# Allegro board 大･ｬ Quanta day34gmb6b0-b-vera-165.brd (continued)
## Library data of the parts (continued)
H19 = H-C394D354P2
H20 = H-TC177BC197D102P2
H22 = H-TC236BC102D102PT
H23 = O-Y11-1
H26 = O-Y12A-7
H27 = O-Y11A-2
H28 = O-Y12A-4
HD17 = 51625-01001-001-10P-L
J1 = SOLDERJUMPER-2
JDIM1 = DDR-DDRRK-20401-TP4B-204P-RUV
JDIM2 = DDR-DDRSK-20401-TP4B-204P-LDV
L3-L6 L8 L12 L14 L16 L36 L39-L41 L44-L46 PR14 PR19 PR68-PR70 PR80 PR97 PR119 PR161 PR165 PR168 PR175 PR176 PR178 PR180 PR186 PR208 PR219 PR220 R90 R265 R326 R328 R331 R337 R339 R341 R343 R347 R350 R355 R380 R397 R400 R409 R414 R621 R628 R7467 = RC0603
L7 L22 L27 L29 = CHOKE-WCM2012-4P
L15 = CHOKE-LQH32PN4R7NN0L
L17-L19 PR104 PR117 PR133 R342 R439 R454 = SHORT0603
L59 L60 PL1 PR7 PR11 PR61 PR237 R151 R338 R532 R598-R600 = RC0805
ODD14 = SATA-202407-2-13P-R
ODD15 = 51605-01801-001-18P-L
PC186 PC201 PC218 PC219 = ECAP5X5_8-5_9-2P
PD9 PD10 = D-DO-214AC
PJP1-PJP4 = SHORT-SOLDERJUMPER-3
PL2 = L3_2X2_5-1_55
PL3-PL7 PL15 PL17-PL19 PR114 PR125 R603 R618 = SHORT0805
PL8 PL16 PL20-PL22 = CHOKE-MPL73-1R5
PL14 = CHOKE-ETQP4L
PQ1 PQ5 PQ9 PQ34 PQ35 PQ40 PQ41 PQ44 Q10 Q13 Q15-Q25 Q29 Q31 Q37 Q39 Q40 Q7030 Q7031 = SOT23_213-3_3-2
PQ6 PQ12-PQ14 PQ18 PQ42 Q1 Q4 Q5 Q26 Q28 Q30 = UMT_213-3-1_3
PQ10 PQ31-PQ33 PQ36 PQ37 = PG-TSDSON-8-8P-R
PQ15 PQ19 PQ29 PQ30 PQ39 = SO-8FL-5P
PQ16 PQ17 Q3 Q12 Q14 Q27 Q34 Q38 Q41 Q820 Q821 = SC70-2_1-65-6P
PQ20 = TO252_134-9_9-4_57-SMT
PQ38 = SOT363-2_1-65-6P
PQ43 PU4 = TSOP6-2_8-95
PR109 PR123 PR127 PR136 PR138 PR158 PR159 PR167 PR170 PR187-PR189 PR221 PR222 = SHORT0201
PR137 PR211 = F3_2X1_65-2_8
PU1 = PVQFN20-3_5X3_5-5-25P
PU3 = QFN28-4X4-4-29P-NCP81101MNTWG
PU5 PU8 = SON14-3X2-4-15P
PU7 = WQFN20-3X3-4-21P
PU10 = QFN23-4X4-5
PU11 PU12 = QFN10-3X3-45
RP1 = 4P2R-0404
RP2-RP6 = 10P8R
TP3-TP6 TP12 TP13 TP21 TP22 TP26 TP27 TP32-TP34 TP36 = TP2650
TP7-TP9 TP23 TP24 TP28-TP30 TP35 = TP2675
TP10 TP11 TP20 TP25 TP31 = TP2050
TP51 = TP1250-P14_4
U2 U17 U22 U26 = SOT23-5
U6 U7 = TRF-9_6-1_27-16P
U8 = QFN32-4X4-4-33P-0_9H
U9 = TQFN16-2X3-4-17P
U10 = QFN16-3X3-5-17P-WM9001
U11 = LQFP128-16X16-4
U12 = VQFN14-3_5X3_5-5-15P
U13 = LGA16-3X3-5-HP3DC2TR
U14 = TSSOP28-6_4-65-29P-1_2H
U15 U8021 = TQFN24-4X4-5-34P
U16 U27 = MSOP8-4_9-65
U18 = TSSOP28-6_4-65
U19 = QFN32-4X4-5-33P-RTS5227-GRT
U20 = QFN48-7X7-5-49P-1H
U21 U28 = PWQFN20-4X4-5-30P
U23 = 91960-0084L-8P-SOCKET
U24 = SOIC8-8-1_27
U25 = BGA1168-INTEL-HASWELL
Y1 = XTL-3_2X2_5-2_2X1_7-0_8H
Y2 Y3 = XTL-3_2X2_5-2_2X1_7
Y4 = XTL-3_2X1_5-2_5-0_8H

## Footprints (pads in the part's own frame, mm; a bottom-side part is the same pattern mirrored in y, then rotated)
4P2R-0404
  rect 0.33x0.762 smd: 1(-0.325,-0.5) 2(-0.325,0.5) 3(0.325,-0.5) 4(0.325,0.5)
10P8R
  rect 0.305x1.092 smd: 1(-1.27,-0.85) 2(-0.635,-0.85) 3(0,-0.85) 4(0.635,-0.85) 5(1.27,-0.85) 6(1.27,0.85) 7(0.635,0.85) 8(0,0.85) 9(-0.635,0.85) 10(-1.27,0.85)
50273-0040L-001-4P-L
  rect 0.787x1.6 smd: 1(-1.875,2.9) 2(-0.625,2.9) 3(0.625,2.9) 4(1.875,2.9)
  rect 2.108x2.997 smd: 5(-4.425,0) 6(4.425,0)
50281-00401-001-4P-L
  rect 0.787x2.007 smd: 1(-1.875,4.05) 2(-0.625,4.05) 3(0.625,4.05) 4(1.875,4.05)
  rect 2.007x2.489 smd: 5(-4.075,0) 6(4.075,0)
50501-03001-001-30P-L
  rect 0.305x1.295 smd: 1(-7.25,2.8) 2(-6.75,2.8) 3(-6.25,2.8) 4(-5.75,2.8) 5(-5.25,2.8) 6(-4.75,2.8) 7(-4.25,2.8) 8(-3.75,2.8) 9(-3.25,2.8) 10(-2.75,2.8) 11(-2.25,2.8) 12(-1.75,2.8) 13(-1.25,2.8) 14(-0.75,2.8) 15(-0.25,2.8) 16(0.25,2.8) 17(0.75,2.8) 18(1.25,2.8) 19(1.75,2.8) 20(2.25,2.8) 21(2.75,2.8) 22(3.25,2.8) 23(3.75,2.8) 24(4.25,2.8) 25(4.75,2.8) 26(5.25,2.8) 27(5.75,2.8) 28(6.25,2.8) 29(6.75,2.8) 30(7.25,2.8)
  rect 1.803x1.397 smd: 31(-8.9,0) 32(8.9,0)
50505-0040N-V01-4P-L
  rect 0.61x1.295 smd: 1(-1.5,3.25) 2(-0.5,3.25) 3(0.5,3.25) 4(1.5,3.25)
  rect 0.991x2.007 smd: 5(-4.1,0) 6(4.1,0)
50519-00801-V01-8P-L
  rect 0.508x1.295 smd: 1(-2.8,3.05) 2(-2,3.05) 3(-1.2,3.05) 4(-0.4,3.05) 5(0.4,3.05) 6(1.2,3.05) 7(2,3.05) 8(2.8,3.05)
  rect 1.803x1.905 smd: 9(-5.1,0) 10(5.1,0)
51540-0404T-001-40P-L
  rect 0.305x0.838 smd: 1(-9.75,3.175) 2(-9.25,3.175) 3(-8.75,3.175) 4(-8.25,3.175) 5(-7.75,3.175) 6(-7.25,3.175) 7(-6.75,3.175) 8(-6.25,3.175) 9(-5.75,3.175) 10(-5.25,3.175) 11(-4.75,3.175) 12(-4.25,3.175) 13(-3.75,3.175) 14(-3.25,3.175) 15(-2.75,3.175) 16(-2.25,3.175) 17(-1.75,3.175) 18(-1.25,3.175) 19(-0.75,3.175) 20(-0.25,3.175) 21(0.25,3.175) 22(0.75,3.175) 23(1.25,3.175) 24(1.75,3.175) 25(2.25,3.175) 26(2.75,3.175) 27(3.25,3.175) 28(3.75,3.175) 29(4.25,3.175) 30(4.75,3.175) 31(5.25,3.175) 32(5.75,3.175) 33(6.25,3.175) 34(6.75,3.175) 35(7.25,3.175) 36(7.75,3.175) 37(8.25,3.175) 38(8.75,3.175) 39(9.25,3.175) 40(9.75,3.175)
  rect 0.787x2.007 smd: 41(-11.45,0) 42(11.45,0)
51586-03241-001-32P-L
  rect 0.406x0.838 smd: 1(-15.5,3.175) 2(-14.5,3.175) 3(-13.5,3.175) 4(-12.5,3.175) 5(-11.5,3.175) 6(-10.5,3.175) 7(-9.5,3.175) 8(-8.5,3.175) 9(-7.5,3.175) 10(-6.5,3.175) 11(-5.5,3.175) 12(-4.5,3.175) 13(-3.5,3.175) 14(-2.5,3.175) 15(-1.5,3.175) 16(-0.5,3.175) 17(0.5,3.175) 18(1.5,3.175) 19(2.5,3.175) 20(3.5,3.175) 21(4.5,3.175) 22(5.5,3.175) 23(6.5,3.175) 24(7.5,3.175) 25(8.5,3.175) 26(9.5,3.175) 27(10.5,3.175) 28(11.5,3.175) 29(12.5,3.175) 30(13.5,3.175) 31(14.5,3.175) 32(15.5,3.175)
  rect 0.787x2.007 smd: 33(-17.7,0) 34(17.7,0)
51605-01801-001-18P-L
  rect 0.305x0.838 smd: 1(-4.25,3.175) 2(-3.75,3.175) 3(-3.25,3.175) 4(-2.75,3.175) 5(-2.25,3.175) 6(-1.75,3.175) 7(-1.25,3.175) 8(-0.75,3.175) 9(-0.25,3.175) 10(0.25,3.175) 11(0.75,3.175) 12(1.25,3.175) 13(1.75,3.175) 14(2.25,3.175) 15(2.75,3.175) 16(3.25,3.175) 17(3.75,3.175) 18(4.25,3.175)
  rect 0.787x2.007 smd: 19(-5.95,0) 20(5.95,0)
51625-01001-001-10P-L
  rect 0.305x0.838 smd: 1(-2.25,3.175) 2(-1.75,3.175) 3(-1.25,3.175) 4(-0.75,3.175) 5(-0.25,3.175) 6(0.25,3.175) 7(0.75,3.175) 8(1.25,3.175) 9(1.75,3.175) 10(2.25,3.175)
  rect 0.787x2.007 smd: 11(-3.95,0) 12(3.95,0)
59012-0080N-003-8P-LDV-SMT
  round 1.27 hole 0.991: 1(-3,-1) 2(-3,1) 3(-1,-1) 4(-1,1) 5(1,-1) 6(1,1) 7(3,-1) 8(3,1)
88266-020L-2P-L-SMT
  rect 0.787x2.007 smd: 1(-0.625,4.05) 2(0.625,4.05)
  rect 1.346x1.6 smd: 3(-2.5,-0.45) 4(2.5,-0.45)
88266-0400-4P-L
  rect 0.787x2.007 smd: 1(-1.875,4.05) 2(-0.625,4.05) 3(0.625,4.05) 4(1.875,4.05)
  rect 2.007x2.489 smd: 5(-4.075,0) 6(4.075,0)
88511-180N-18P-L
  rect 0.305x1.295 smd: 1(-4.25,2.8) 2(-3.75,2.8) 3(-3.25,2.8) 4(-2.75,2.8) 5(-2.25,2.8) 6(-1.75,2.8) 7(-1.25,2.8) 8(-0.75,2.8) 9(-0.25,2.8) 10(0.25,2.8) 11(0.75,2.8) 12(1.25,2.8) 13(1.75,2.8) 14(2.25,2.8) 15(2.75,2.8) 16(3.25,2.8) 17(3.75,2.8) 18(4.25,2.8)
  rect 1.803x1.397 smd: 19(-5.9,0) 20(5.9,0)
88513-0601-6P-L-SMT
  rect 0.508x1.6 smd: 1(-2.5,2.95) 2(-1.5,2.95) 3(-0.5,2.95) 4(0.5,2.95) 5(1.5,2.95) 6(2.5,2.95)
  rect 1.803x1.397 smd: 7(-4.65,0) 8(4.65,0)
88513-2001-20P-L
  rect 0.508x1.295 smd: 1(-9.5,0) 2(-8.5,0) 3(-7.5,0) 4(-6.5,0) 5(-5.5,0) 6(-4.5,0) 7(-3.5,0) 8(-2.5,0) 9(-1.5,0) 10(-0.5,0) 11(0.5,0) 12(1.5,0) 13(2.5,0) 14(3.5,0) 15(4.5,0) 16(5.5,0) 17(6.5,0) 18(7.5,0) 19(8.5,0) 20(9.5,0)
  rect 1.803x1.397 smd: 21(-11.65,-2.8) 22(11.65,-2.8)
91960-0084L-8P-SOCKET
  rect 0.889x1.346 smd: 1(1.905,3.675) 2(0.635,3.675) 3(-0.635,3.675) 4(-1.905,3.675) 5(-1.905,-3.675) 6(-0.635,-3.675) 7(0.635,-3.675) 8(1.905,-3.675)
BAT-23_2-4_2
  round 0.787 hole 0.787 unplated: (0,-8)
  round 1.194 hole 1.194 unplated: (0,8)
  rect 2.007x3.988 smd: 1(14.5,0) 2(-15.8,0)
BAT-PMPCRT-08MLBK2ZZ4H0-8P-L
  round 1.6 hole 0.991: 1(-7,0) 2(-5,0) 3(-3,0) 4(-1,0) 5(1,0) 6(3,0) 7(5,0) 8(7,0)
  oval 2.007x3.607 hole 0.787x2.692: 9(-9.625,1.2) 10(9.625,0)
  round 4.216 hole 3.2: 11(14.75,-6.8)
BAT-PMPCRT-08MLBK2ZZ4H1-8P-L
  round 1.6 hole 0.991: 1(-7,0) 2(-5,0) 3(-3,0) 4(-1,0) 5(1,0) 6(3,0) 7(5,0) 8(7,0)
  oval 2.007x3.607 hole 0.787x2.692: 9(-9.625,1.2) 10(9.625,0)
  round 4.216 hole 3.2: 11(19,0.7)
BGA1168-INTEL-HASWELL
  round 0.508 smd: A3(18.177,-11.314) A62(-18.722,-11.314) AW1(19.314,10.727) AW63(-19.314,10.743) AY2(18.771,11.314) AY62(-18.748,11.314) B2(18.806,-10.806) B63(-19.314,-10.722) C1(19.314,-10.177)
  round 0.381 smd: A4(17.421,-11.314) A5(16.76,-11.314) A6(15.564,-11.314) A59(-16.586,-11.314) A60(-17.412,-11.314) A61(-18.072,-11.314) AA9(14.282,0.262) AA21(7.627,0.175) AA23(6.199,0.175) AA58(-16.063,0.015) AB10(13.838,0.738) AB20(8.135,0.582) AB21(7.627,0.988) AB22(6.707,0.582) AB23(6.199,0.988) AB57(-15.743,0.666) AC9(14.282,1.215) AC20(8.135,1.394) AC22(6.707,1.394) AC58(-16.063,1.316) AD10(13.838,1.691) AD21(7.627,1.801) AD23(6.199,1.801) AD57(-15.743,1.966) AE9(14.282,2.167) AE10(13.838,2.643) AE20(8.135,2.207) AE21(7.627,2.614) AE22(6.707,2.207) AE23(6.199,2.614) AE58(-16.063,2.616) AF9(14.282,3.12) AF11(13.255,2.968) AF12(12.442,2.968) AF14(11.63,2.968) AF15(10.817,2.968) AF17(10.004,2.968) AF18(9.191,2.968) AF20(8.378,2.968) AF22(6.707,3.02) AG10(13.662,3.476) AG11(12.849,3.476) AG13(12.036,3.476) AG14(11.223,3.476) AG16(10.41,3.476) AG17(9.598,3.476) AG19(8.785,3.476) AG20(7.972,3.476) AG23(6.199,3.426) AG57(-15.743,3.267) AG58(-16.377,3.695) AH22(6.707,3.833) AH24(5.394,3.975) AH26(4.094,3.975) AH28(2.793,3.975) AH30(1.493,3.975) AH32(0.192,3.975) AH34(-1.108,3.975) AH36(-2.409,3.975) AH38(-3.709,3.975) AH40(-5.01,3.975) AH42(-6.31,3.975) AH44(-7.611,3.975) AH46(-8.911,3.975) AH49(-10.212,3.975) AH51(-11.512,3.975) AH53(-12.813,3.975) AH55(-14.113,3.975) AH57(-15.413,3.975) AJ23(6.199,4.239) AJ25(4.744,4.3) AJ27(3.443,4.3) AJ29(2.143,4.3) AJ31(0.843,4.3) AJ33(-0.458,4.3) AJ35(-1.758,4.3) AJ37(-3.059,4.3) AJ39(-4.359,4.3) AJ41(-5.66,4.3) AJ43(-6.96,4.3) AJ45(-8.261,4.3) AJ47(-9.561,4.3) AJ50(-10.862,4.3) AJ52(-12.162,4.3) AJ54(-13.463,4.3) AJ56(-14.763,4.3) AJ58(-16.064,4.3) AT1(19.314,8.683) AT63(-19.314,8.533) AU1(19.314,9.343) AU63(-19.314,9.359) AV1(19.314,10.004) AV2(18.654,9.993) AV62(-18.664,10.004) AV63(-19.314,10.019) AW2(18.654,10.654) AW3(17.993,10.654) AW61(-18.014,10.664) AW62(-18.664,10.664) AY3(18.047,11.314) AY4(17.387,11.314) AY5(16.726,11.314) AY59(-16.774,11.314) AY60(-17.434,11.314) AY61(-18.095,11.314) B3(18.056,-10.664) B61(-18.001,-10.654) B62(-18.664,-10.59) C2(18.664,-10.056) C62(-18.664,-9.93) C63(-19.314,-9.998) D1(19.314,-9.453) D63(-19.314,-9.338) E1(19.314,-8.792) E23(5.981,-8.713) E25(4.6,-8.713) E27(3.474,-8.713) E29(2.093,-8.713) E31(0.966,-8.713) E33(-0.415,-8.713) E35(-1.541,-8.713) E37(-2.922,-8.713) E39(-4.049,-8.713) E41(-5.43,-8.713) E43(-6.556,-8.713) E45(-7.937,-8.713) E47(-9.064,-8.713) E49(-10.444,-8.713) E51(-11.571,-8.713) E53(-12.952,-8.713) E55(-14.079,-8.713) E57(-15.459,-8.713) E63(-19.314,-8.667) F1(19.314,-7.878) F22(6.597,-8.256) F24(5.291,-8.188) F26(4.037,-8.188) F28(2.783,-8.188) F30(1.53,-8.188) F32(0.276,-8.188) F34(-0.978,-8.188) F36(-2.232,-8.188) F38(-3.485,-8.188) F40(-4.739,-8.188) F42(-5.993,-8.188) F44(-7.247,-8.188) F46(-8.5,-8.188) F48(-9.754,-8.188) F50(-11.008,-8.188) F52(-12.262,-8.188) F54(-13.515,-8.188) F56(-14.769,-8.188) F58(-16.063,-8.188) G22(6.707,-7.546) G23(5.981,-7.863) G25(4.6,-7.863) G27(3.474,-7.863) G29(2.093,-7.863) G31(0.966,-7.863) G33(-0.415,-7.863) G35(-1.541,-7.863) G37(-2.922,-7.863) G39(-4.049,-7.863) G41(-5.43,-7.863) G43(-6.556,-7.863) G45(-7.937,-7.863) G47(-9.064,-7.863) G49(-10.444,-7.863) G51(-11.571,-7.863) G53(-12.952,-7.863) G55(-14.079,-7.863) G57(-15.459,-7.863) H22(6.707,-6.734) H23(6.199,-7.14) H57(-15.743,-7.213) J22(6.707,-5.921) J23(6.199,-6.327) J58(-16.063,-6.487) K9(14.282,-5.453) K10(13.379,-5.614) K12(12.426,-5.614) K14(11.474,-5.614) K16(10.521,-5.614) K18(9.569,-5.614) K19(8.616,-5.614) K21(7.664,-5.614) K23(6.199,-5.514) K57(-15.743,-5.837) L10(13.838,-4.977) L11(12.902,-5.17) L13(11.95,-5.17) L15(10.997,-5.17) L17(10.045,-5.17) L18(9.092,-5.17) L20(8.135,-5.108) L22(6.707,-5.108) L58(-16.063,-5.186) M9(14.282,-4.5) M20(8.135,-4.295) M21(7.627,-4.702) M22(6.707,-4.295) M23(6.199,-4.702) M57(-15.743,-4.536) N10(13.838,-4.024) N21(7.627,-3.889) N23(6.199,-3.889) N58(-16.063,-3.886) P9(14.282,-3.548) P20(8.135,-3.482) P22(6.707,-3.482) P57(-15.743,-3.236) R10(13.838,-3.072) R20(8.135,-2.67) R21(7.627,-3.076) R22(6.707,-2.67) R23(6.199,-3.076) T9(14.282,-2.595) T21(7.627,-2.263) T23(6.199,-2.263) T58(-16.063,-2.585) U9(14.282,-1.643) U10(13.838,-2.119) U20(8.135,-1.857) U22(6.707,-1.857) U57(-15.743,-1.935) V10(13.838,-1.167) V21(7.627,-1.45) V23(6.199,-1.45) V58(-16.063,-1.285) W9(14.282,-0.69) W20(8.135,-1.044) W21(7.627,-0.638) W22(6.707,-1.044) W23(6.199,-0.638) W57(-15.743,-0.635) Y10(13.838,-0.214) Y20(8.135,-0.231) Y22(6.707,-0.231)
  round 0.305 smd: A8(14.776,-11.314) A9(13.862,-11.314) A11(12.948,-11.314) A12(12.198,-11.314) A14(11.284,-11.314) A15(10.37,-11.314) A17(9.62,-11.314) A18(8.706,-11.314) A20(7.791,-11.314) A21(7.042,-11.314) A23(6.128,-11.314) A24(5.291,-10.989) A25(4.6,-11.314) A27(3.474,-11.314) A28(2.783,-10.989) A29(2.093,-11.314) A31(0.966,-11.314) A32(0.276,-10.989) A33(-0.415,-11.314) A35(-1.541,-11.314) A36(-2.232,-10.989) A37(-2.922,-11.314) A39(-4.049,-11.314) A40(-4.739,-10.989) A41(-5.43,-11.314) A43(-6.556,-11.314) A44(-7.247,-10.989) A45(-7.937,-11.314) A47(-9.064,-11.314) A48(-9.754,-10.989) A49(-10.444,-11.314) A51(-11.571,-11.314) A52(-12.262,-10.989) A53(-12.952,-11.314) A55(-14.079,-11.314) A56(-14.769,-10.989) A57(-15.459,-11.314) AA1(19.314,0.402) AA2(18.664,0.402) AA3(18.014,0.364) AA4(17.363,0.364) AA59(-16.713,0.324) AA60(-17.363,0.324) AA61(-18.014,0.324) AA62(-18.664,0.362) AA63(-19.314,0.362) AB5(16.678,0.738) AB6(16.027,0.738) AB7(15.377,0.738) AB8(14.727,0.738) AC1(19.314,1.152) AC2(18.664,1.152) AC3(18.014,1.19) AC4(17.363,1.19) AC59(-16.713,1.15) AC60(-17.363,1.15) AC61(-18.014,1.15) AC62(-18.664,1.112) AC63(-19.314,1.112) AD1(19.314,1.901) AD2(18.664,1.901) AD3(18.014,1.863) AD4(17.363,1.863) AD5(16.678,1.691) AD6(16.027,1.691) AD7(15.377,1.691) AD8(14.727,1.691) AD59(-16.713,1.823) AD60(-17.363,1.823) AD61(-18.014,1.823) AD62(-18.664,1.861) AD63(-19.314,1.861) AE5(16.678,2.643) AE6(16.027,2.643) AE7(15.377,2.643) AE8(14.727,2.643) AE59(-16.713,2.648) AE60(-17.363,2.648) AE61(-18.014,2.648) AE62(-18.664,2.61) AE63(-19.314,2.61) AF1(19.314,2.65) AF2(18.664,2.65) AF3(18.014,2.688) AF4(17.363,2.688) AG1(19.314,3.4) AG2(18.664,3.4) AG3(18.014,3.361) AG4(17.363,3.361) AG5(16.678,3.596) AG6(16.027,3.596) AG7(15.377,3.596) AG8(14.727,3.596) AG21(7.359,3.807) AG60(-17.038,3.288) AG61(-17.689,3.288) AG62(-18.339,3.288) AG63(-18.989,3.288) AH1(19.314,4.149) AH2(18.664,4.149) AH3(18.014,4.187) AH4(17.363,4.187) AH10(13.662,4.162) AH11(12.849,4.162) AH13(12.036,4.162) AH14(11.223,4.162) AH16(10.41,4.162) AH17(9.598,4.162) AH19(8.785,4.162) AH20(7.972,4.162) AH60(-17.363,3.964) AH61(-18.014,3.964) AH62(-18.664,3.964) AH63(-19.314,3.964) AJ5(16.678,4.548) AJ6(16.027,4.548) AJ7(15.377,4.548) AJ8(14.727,4.548) AJ10(13.662,4.812) AJ11(12.849,4.812) AJ13(12.036,4.812) AJ14(11.223,4.812) AJ60(-17.038,4.64) AJ61(-17.689,4.64) AJ62(-18.339,4.64) AJ63(-18.989,4.64) AK1(19.314,4.898) AK2(18.664,4.898) AK3(18.014,4.86) AK4(17.363,4.86) AK8(15.011,5.137) AK18(9.466,4.952) AK20(8.513,4.952) AK21(7.561,4.952) AK60(-17.363,5.209) AK61(-18.014,5.209) AK62(-18.664,5.315) AK63(-19.314,5.315) AL1(19.314,5.647) AL2(18.664,5.647) AL3(18.014,5.686) AL4(17.363,5.686) AL5(16.413,5.462) AL7(15.575,5.462) AL8(15.011,5.787) AL10(13.657,5.462) AL11(13.093,5.787) AL13(11.738,5.462) AL15(11.174,5.787) AL17(10.092,5.268) AL18(9.466,5.602) AL20(8.513,5.602) AL21(7.561,5.602) AL22(6.608,5.602) AL23(5.786,5.602) AL25(4.81,5.602) AL26(3.858,5.602) AL28(2.905,5.602) AL29(1.953,5.602) AL31(1.054,5.277) AL32(0.49,5.602) AL33(-0.412,5.602) AL35(-1.415,5.602) AL36(-2.266,5.602) AL38(-3.32,5.602) AL39(-4.228,5.277) AL40(-4.817,5.602) AL42(-5.63,5.602) AL43(-6.582,5.602) AL45(-7.56,5.602) AL46(-8.487,5.602) AL48(-9.542,5.602) AL49(-10.443,5.602) AL51(-11.447,5.602) AL52(-12.269,5.602) AL54(-13.295,5.602) AL55(-14.248,5.602) AL57(-15.195,5.602) AL58(-16.094,5.602) AL60(-17.038,5.855) AL61(-17.689,5.855) AM1(19.314,6.397) AM2(18.664,6.397) AM3(18.014,6.359) AM4(17.363,6.359) AM5(16.413,6.112) AM7(15.575,6.112) AM8(15.011,6.437) AM10(13.657,6.112) AM11(13.093,6.437) AM13(11.738,6.112) AM15(11.174,6.437) AM17(10.092,5.919) AM18(9.466,6.252) AM20(8.513,6.252) AM21(7.561,6.252) AM22(6.608,6.252) AM23(5.786,6.252) AM25(4.81,6.252) AM26(3.858,6.252) AM28(2.905,6.252) AM29(1.953,6.252) AM31(1.054,5.927) AM32(0.49,6.252) AM33(-0.412,6.252) AM35(-1.415,6.252) AM36(-2.266,6.252) AM38(-3.32,6.252) AM40(-4.817,6.252) AM42(-5.63,6.252) AM43(-6.582,6.252) AM45(-7.56,6.252) AM46(-8.487,6.252) AM48(-9.542,6.252) AM49(-10.443,6.252) AM51(-11.447,6.252) AM52(-12.269,6.252) AM54(-13.295,6.252) AM55(-14.248,6.252) AM57(-15.195,6.252) AM58(-16.094,6.252) AM60(-17.363,6.501) AM61(-18.014,6.501) AM62(-18.664,6.395) AM63(-19.314,6.395) AN1(19.314,7.146) AN2(18.664,7.146) AN3(18.014,7.184) AN4(17.363,7.184) AN5(16.413,6.762) AN7(15.575,6.762) AN8(15.011,7.088) AN10(13.657,6.762) AN11(13.093,7.088) AN13(11.738,6.762) AN15(11.174,7.088) AN17(10.092,6.569) AN18(9.466,6.903) AN20(8.513,6.903) AN21(7.561,6.903) AN22(6.608,6.903) AN23(5.786,6.903) AN25(4.81,6.903) AN26(3.858,6.903) AN28(2.905,6.903) AN29(1.953,6.903) AN31(1.054,6.578) AN32(0.49,6.903) AN33(-0.412,6.903) AN35(-1.415,6.903) AN36(-2.266,6.903) AN38(-3.32,6.903) AN39(-4.228,6.578) AN40(-4.817,6.903) AN42(-5.63,6.903) AN43(-6.582,6.903) AN45(-7.56,6.903) AN46(-8.487,6.903) AN48(-9.542,6.903) AN49(-10.443,6.903) AN51(-11.447,6.903) AN52(-12.269,6.903) AN54(-13.295,6.903) AN55(-14.248,6.903) AN57(-15.195,6.903) AN58(-16.094,6.903) AN60(-17.038,7.07) AN61(-17.689,7.07) AN62(-18.339,7.07) AN63(-18.989,7.07) AP1(19.314,7.895) AP2(18.664,7.895) AP3(18.014,7.857) AP4(17.363,7.857) AP5(16.413,7.413) AP7(15.575,7.413) AP8(15.011,7.738) AP10(13.657,7.413) AP11(13.093,7.738) AP13(11.738,7.413) AP15(11.174,7.738) AP17(10.092,7.219) AP18(9.466,7.553) AP20(8.513,7.553) AP21(7.561,7.553) AP22(6.608,7.553) AP23(5.786,7.553) AP25(4.81,7.553) AP26(3.858,7.553) AP28(2.905,7.553) AP29(1.953,7.553) AP31(1.054,7.228) AP32(0.49,7.553) AP33(-0.412,7.553) AP35(-1.415,7.553) AP36(-2.266,7.553) AP38(-3.32,7.553) AP39(-4.228,7.228) AP40(-4.817,7.553) AP42(-5.63,7.553) AP43(-6.582,7.553) AP45(-7.56,7.553) AP46(-8.487,7.553) AP48(-9.542,7.553) AP49(-10.443,7.553) AP51(-11.447,7.553) AP52(-12.269,7.553) AP54(-13.295,7.553) AP55(-14.248,7.553) AP57(-15.195,7.553) AP58(-16.094,7.553) AP60(-17.363,7.746) AP61(-18.014,7.746) AP62(-18.664,7.746) AP63(-19.314,7.746) AR5(16.413,8.063) AR7(15.575,8.063) AR8(15.011,8.388) AR10(13.657,8.063) AR11(13.093,8.388) AR13(11.738,8.063) AR15(11.174,8.388) AR17(10.092,7.869) AR18(9.466,8.203) AR20(8.513,8.203) AR21(7.561,8.203) AR22(6.608,8.203) AR23(5.786,8.203) AR25(4.81,8.203) AR26(3.858,8.203) AR28(2.905,8.203) AR29(1.953,8.203) AR31(1.054,7.878) AR32(0.49,8.203) AR33(-0.412,8.203) AR35(-1.415,8.203) AR36(-2.266,8.203) AR38(-3.32,8.203) AR39(-4.228,7.878) AR40(-4.817,8.203) AR42(-5.63,8.203) AR43(-6.582,8.203) AR45(-7.56,8.203) AR46(-8.487,8.203) AR48(-9.542,8.203) AR49(-10.443,8.203) AR51(-11.447,8.203) AR52(-12.269,8.203) AR54(-13.295,8.203) AR55(-14.248,8.203) AR57(-15.195,8.203) AR58(-16.094,8.203) AT2(18.664,8.645) AT3(18.014,8.683) AT4(17.363,8.683) AT5(16.413,8.713) AT7(15.575,8.713) AT10(13.657,8.713) AT13(11.738,8.713) AT35(-1.122,8.905) AT37(-2.697,8.905) AT40(-4.272,8.905) AT42(-5.847,8.905) AT43(-7.422,8.905) AT46(-8.996,8.905) AT49(-10.597,8.933) AT61(-17.689,8.32) AT62(-18.498,8.376) AU2(18.659,9.333) AU3(17.999,9.333) AU4(17.338,9.333) AU6(15.977,9.363) AU7(15.151,9.363) AU8(14.478,9.363) AU10(13.653,9.363) AU11(12.98,9.363) AU12(12.154,9.363) AU14(11.481,9.363) AU15(10.656,9.363) AU16(10.092,9.038) AU17(9.454,9.363) AU18(8.778,9.038) AU19(8.21,9.363) AU20(7.563,9.038) AU21(6.917,9.363) AU22(6.348,9.038) AU23(5.672,9.363) AU24(4.996,9.038) AU25(4.321,9.363) AU26(3.645,9.038) AU27(3.076,9.363) AU28(2.43,9.038) AU29(1.783,9.363) AU30(1.214,9.038) AU31(0.539,9.363) AU33(-0.058,9.016) AU34(-0.66,9.363) AU35(-1.585,9.363) AU36(-2.235,9.363) AU37(-3.16,9.363) AU39(-3.81,9.363) AU40(-4.734,9.363) AU41(-5.385,9.363) AU42(-6.309,9.363) AU43(-6.959,9.363) AU44(-7.884,9.363) AU46(-8.534,9.363) AU47(-9.459,9.363) AU49(-10.109,9.363) AU50(-11.086,9.363) AU51(-11.666,9.038) AU52(-12.342,9.363) AU53(-13.017,9.038) AU54(-13.586,9.363) AU55(-14.233,9.038) AU56(-14.879,9.363) AU57(-15.448,9.038) AU58(-16.124,9.363) AU59(-16.688,9.038) AU60(-17.251,9.363) AU61(-17.963,9.087) AU62(-18.664,9.349) AV3(17.993,9.993) AV4(17.338,9.993) AV5(16.65,10.014) AV6(15.977,10.014) AV7(15.151,10.014) AV8(14.478,10.014) AV10(13.653,10.014) AV11(12.98,10.014) AV12(12.154,10.014) AV14(11.481,10.014) AV15(10.656,10.014) AV16(10.092,9.689) AV17(9.454,10.014) AV18(8.778,9.689) AV19(8.21,10.014) AV20(7.563,9.689) AV21(6.917,10.014) AV22(6.348,9.689) AV23(5.672,10.014) AV24(4.996,9.689) AV25(4.321,10.014) AV26(3.645,9.689) AV27(3.076,10.014) AV28(2.43,9.689) AV29(1.783,10.014) AV30(1.214,9.689) AV31(0.539,10.014) AV33(-0.086,9.689) AV34(-0.71,10.014) AV35(-1.535,10.014) AV36(-2.284,10.014) AV37(-3.11,10.014) AV39(-3.859,10.014) AV40(-4.685,10.014) AV41(-5.434,10.014) AV42(-6.26,10.014) AV43(-7.009,10.014) AV44(-7.834,10.014) AV46(-8.584,10.014) AV47(-9.409,10.014) AV49(-10.158,10.014) AV50(-10.984,10.014) AV51(-11.666,9.689) AV52(-12.342,10.014) AV53(-13.017,9.689) AV54(-13.586,10.014) AV55(-14.233,9.689) AV56(-14.879,10.014) AV57(-15.448,9.689) AV58(-16.124,10.014) AV59(-16.688,9.689) AV60(-17.251,10.014) AV61(-17.988,9.737) AW4(17.338,10.654) AW5(16.688,10.664) AW6(15.939,10.664) AW7(15.189,10.664) AW8(14.44,10.664) AW10(13.691,10.664) AW11(12.942,10.664) AW12(12.192,10.664) AW14(11.443,10.664) AW15(10.694,10.664) AW16(10.092,10.339) AW17(9.454,10.664) AW18(8.778,10.339) AW19(8.103,10.664) AW21(7.023,10.664) AW22(6.348,10.339) AW23(5.672,10.664) AW24(4.996,10.339) AW25(4.321,10.664) AW26(3.645,10.339) AW27(2.97,10.664) AW29(1.89,10.664) AW30(1.214,10.339) AW31(0.539,10.664) AW33(-0.137,10.339) AW34(-0.71,10.664) AW35(-1.535,10.664) AW36(-2.284,10.664) AW37(-3.11,10.664) AW39(-3.859,10.664) AW40(-4.685,10.664) AW41(-5.434,10.664) AW42(-6.26,10.664) AW43(-7.009,10.664) AW44(-7.834,10.664) AW46(-8.584,10.664) AW47(-9.409,10.664) AW49(-10.158,10.664) AW50(-10.984,10.664) AW51(-11.666,10.339) AW52(-12.342,10.664) AW53(-13.017,10.339) AW54(-13.693,10.664) AW56(-14.772,10.664) AW57(-15.448,10.339) AW58(-16.124,10.664) AW59(-16.688,10.339) AW60(-17.251,10.664) AY6(15.939,11.314) AY7(15.189,11.314) AY8(14.44,11.314) AY10(13.691,11.314) AY11(12.942,11.314) AY12(12.192,11.314) AY14(11.443,11.314) AY15(10.694,11.314) AY16(10.13,10.989) AY17(9.454,11.314) AY18(8.778,10.989) AY19(8.103,11.314) AY21(7.023,11.314) AY22(6.348,10.989) AY23(5.672,11.314) AY24(4.996,10.989) AY25(4.321,11.314) AY26(3.645,10.989) AY27(2.97,11.314) AY29(1.89,11.314) AY30(1.214,10.989) AY31(0.539,11.314) AY33(-0.137,10.989) AY34(-0.71,11.314) AY35(-1.535,11.314) AY36(-2.284,11.314) AY37(-3.11,11.314) AY39(-3.859,11.314) AY40(-4.685,11.314) AY41(-5.434,11.314) AY42(-6.26,11.314) AY43(-7.009,11.314) AY44(-7.834,11.314) AY46(-8.584,11.314) AY47(-9.409,11.314) AY49(-10.158,11.314) AY50(-10.984,11.314) AY51(-11.666,10.989) AY52(-12.342,11.314) AY53(-13.017,10.989) AY54(-13.693,11.314) AY56(-14.772,11.314) AY57(-15.448,10.989) AY58(-16.124,11.314) B4(17.393,-10.664) B5(16.176,-10.672) B6(15.196,-10.672) B8(14.423,-10.672) B9(13.598,-10.672) B11(12.617,-10.672) B12(11.845,-10.672) B14(11.02,-10.672) B15(10.039,-10.672) B17(9.267,-10.672) B18(8.442,-10.672) B20(7.461,-10.672) B21(7.042,-10.118) B22(6.689,-10.672) B23(5.864,-10.672) B24(5.291,-10.339) B25(4.6,-10.664) B26(4.037,-10.339) B27(3.474,-10.664) B28(2.783,-10.339) B29(2.093,-10.664) B30(1.53,-10.339) B31(0.966,-10.664) B32(0.276,-10.339) B33(-0.415,-10.664) B34(-0.978,-10.339) B35(-1.541,-10.664) B36(-2.232,-10.339) B37(-2.922,-10.664) B38(-3.485,-10.339) B39(-4.049,-10.664) B40(-4.739,-10.339) B41(-5.43,-10.664) B42(-5.993,-10.339) B43(-6.556,-10.664) B44(-7.247,-10.339) B45(-7.937,-10.664) B46(-8.5,-10.339) B47(-9.064,-10.664) B48(-9.754,-10.339) B49(-10.444,-10.664) B50(-11.008,-10.339) B51(-11.571,-10.664) B52(-12.262,-10.339) B53(-12.952,-10.664) B54(-13.515,-10.339) B55(-14.079,-10.664) B56(-14.769,-10.339) B57(-15.459,-10.664) B58(-16.023,-10.339) B59(-16.586,-10.664) B60(-17.351,-10.654) C3(18.012,-10.012) C4(17.196,-10.042) C5(16.542,-10.118) C6(15.538,-10.118) C8(14.776,-10.118) C9(13.964,-10.118) C11(12.96,-10.118) C12(12.198,-10.118) C14(11.386,-10.118) C15(10.382,-10.118) C17(9.62,-10.118) C18(8.807,-10.118) C20(7.804,-10.118) C21(7.423,-9.529) C22(6.636,-9.529) C23(6.229,-10.118) C24(5.263,-9.282) C25(4.6,-10.014) C26(4.037,-9.689) C27(3.474,-10.014) C28(2.756,-9.282) C29(2.093,-10.014) C30(1.53,-9.689) C31(0.966,-10.014) C32(0.248,-9.282) C33(-0.415,-10.014) C34(-0.978,-9.689) C35(-1.541,-10.014) C36(-2.259,-9.282) C37(-2.922,-10.014) C38(-3.485,-9.689) C39(-4.049,-10.014) C40(-4.767,-9.282) C41(-5.43,-10.014) C42(-5.993,-9.689) C43(-6.556,-10.014) C44(-7.274,-9.282) C45(-7.937,-10.014) C46(-8.5,-9.689) C47(-9.064,-10.014) C48(-9.756,-9.282) C49(-10.444,-10.014) C50(-11.008,-9.689) C51(-11.571,-10.014) C52(-12.264,-9.323) C53(-12.952,-10.014) C54(-13.515,-9.689) C55(-14.079,-10.014) C56(-14.771,-9.323) C57(-15.459,-10.014) C58(-16.023,-9.689) C59(-16.586,-10.014) C61(-17.689,-10.077) D2(18.664,-9.24) D3(18.014,-9.278) D5(16.636,-9.472) D6(15.945,-9.529) D8(15.157,-9.529) D9(14.37,-9.529) D11(13.462,-9.529) D12(12.579,-9.529) D14(11.792,-9.529) D15(10.884,-9.529) D17(10.001,-9.529) D18(9.214,-9.529) D20(8.306,-9.529) D21(7.079,-8.891) D23(5.937,-9.529) D25(4.6,-9.363) D26(4.037,-9.038) D27(3.474,-9.363) D29(2.093,-9.363) D30(1.53,-9.038) D31(0.966,-9.363) D33(-0.415,-9.363) D34(-0.978,-9.038) D35(-1.541,-9.363) D37(-2.922,-9.363) D38(-3.485,-9.038) D39(-4.049,-9.363) D41(-5.43,-9.363) D42(-5.993,-9.038) D43(-6.556,-9.363) D45(-7.937,-9.363) D46(-8.5,-9.038) D47(-9.064,-9.363) D49(-10.444,-9.363) D50(-11.008,-9.038) D51(-11.571,-9.363) D53(-12.952,-9.363) D54(-13.515,-9.038) D55(-14.079,-9.363) D57(-15.459,-9.363) D58(-16.023,-9.038) D59(-16.586,-9.363) D60(-17.363,-9.513) D61(-18.014,-9.513) D62(-18.664,-9.28) E2(18.664,-8.589) E3(18.014,-8.627) E4(17.363,-8.627) E5(16.712,-8.695) E6(15.76,-8.695) E8(14.807,-8.695) E10(13.855,-8.695) E11(12.902,-8.695) E13(11.95,-8.695) E15(10.997,-8.695) E17(10.045,-8.695) E18(9.092,-8.695) E20(8.14,-8.695) E59(-16.713,-8.667) E60(-17.363,-8.667) E61(-18.014,-8.667) E62(-18.664,-8.629) F2(18.664,-7.84) F3(18.014,-7.802) F4(17.363,-7.802) F5(16.712,-8.045) F6(15.76,-8.045) F8(14.807,-8.045) F10(13.855,-8.045) F11(12.902,-8.045) F13(11.95,-8.045) F15(10.997,-8.045) F17(10.045,-8.045) F18(9.092,-8.045) F20(8.14,-8.045) F59(-16.713,-7.842) F60(-17.363,-7.842) F61(-18.014,-7.842) F62(-18.664,-7.88) F63(-19.314,-7.88) G1(19.314,-7.091) G2(18.664,-7.091) G3(18.014,-7.129) G4(17.363,-7.129) G5(16.712,-7.395) G6(15.76,-7.395) G8(14.807,-7.395) G10(13.855,-7.395) G11(12.902,-7.395) G13(11.95,-7.395) G15(10.997,-7.395) G17(10.045,-7.395) G18(9.092,-7.395) G20(8.14,-7.395) H5(16.712,-6.745) H6(15.76,-6.745) H8(14.807,-6.745) H10(13.855,-6.745) H11(12.902,-6.745) H13(11.95,-6.745) H15(10.997,-6.745) H17(10.045,-6.745) H18(9.092,-6.745) H20(8.14,-6.745) H59(-16.713,-7.169) H60(-17.363,-7.169) H61(-18.014,-7.169) H62(-18.664,-7.131) H63(-19.314,-7.131) J1(19.314,-6.341) J2(18.664,-6.341) J3(18.014,-6.303) J4(17.363,-6.303) J5(16.687,-6.094) J6(15.747,-6.094) J8(14.807,-6.094) J10(13.855,-6.094) J11(12.902,-6.094) J13(11.95,-6.094) J15(10.997,-6.094) J17(10.045,-6.094) J18(9.092,-6.094) J20(8.14,-6.094) J21(7.219,-6.328) J59(-16.713,-6.343) J60(-17.363,-6.343) J61(-18.014,-6.343) J62(-18.664,-6.381) J63(-19.314,-6.381) K1(19.314,-5.592) K2(18.664,-5.592) K3(18.014,-5.63) K4(17.363,-5.63) K59(-16.713,-5.67) K60(-17.363,-5.67) K61(-18.014,-5.67) K62(-18.664,-5.632) K63(-19.314,-5.632) L1(19.314,-4.843) L2(18.664,-4.843) L3(18.014,-4.805) L4(17.363,-4.805) L5(16.678,-4.977) L6(16.027,-4.977) L7(15.377,-4.977) L8(14.727,-4.977) L59(-16.713,-4.845) L60(-17.363,-4.845) L61(-18.014,-4.845) L62(-18.664,-4.883) L63(-19.314,-4.883) N1(19.314,-4.093) N2(18.664,-4.093) N3(18.014,-4.132) N4(17.363,-4.132) N5(16.678,-4.024) N6(16.027,-4.024) N7(15.377,-4.024) N8(14.727,-4.024) N59(-16.713,-4.172) N60(-17.363,-4.172) N61(-18.014,-4.172) N62(-18.664,-4.134) N63(-19.314,-4.134) P1(19.314,-3.344) P2(18.664,-3.344) P3(18.014,-3.306) P4(17.363,-3.306) P59(-16.713,-3.346) P60(-17.363,-3.346) P61(-18.014,-3.346) P62(-18.664,-3.384) P63(-19.314,-3.384) R5(16.678,-3.072) R6(16.027,-3.072) R7(15.377,-3.072) R8(14.727,-3.072) T1(19.314,-2.595) T2(18.664,-2.595) T3(18.014,-2.633) T4(17.363,-2.633) T59(-16.713,-2.673) T60(-17.363,-2.673) T61(-18.014,-2.673) T62(-18.664,-2.635) T63(-19.314,-2.635) U1(19.314,-1.846) U2(18.664,-1.846) U3(18.014,-1.807) U4(17.363,-1.807) U5(16.678,-2.119) U6(16.027,-2.119) U7(15.377,-2.119) U8(14.727,-2.119) U59(-16.713,-1.848) U60(-17.363,-1.848) U61(-18.014,-1.848) U62(-18.664,-1.886) U63(-19.314,-1.886) V1(19.314,-1.096) V2(18.664,-1.096) V3(18.014,-1.134) V4(17.363,-1.134) V5(16.678,-1.167) V6(16.027,-1.167) V7(15.377,-1.167) V8(14.727,-1.167) V59(-16.713,-1.174) V60(-17.363,-1.174) V61(-18.014,-1.174) V62(-18.664,-1.136) V63(-19.314,-1.136) Y1(19.314,-0.347) Y2(18.664,-0.347) Y3(18.014,-0.309) Y4(17.363,-0.309) Y5(16.678,-0.214) Y6(16.027,-0.214) Y7(15.377,-0.214) Y8(14.727,-0.214) Y59(-16.713,-0.349) Y60(-17.363,-0.349) Y61(-18.014,-0.349) Y62(-18.664,-0.387) Y63(-19.314,-0.387)
  round 0.33 smd: AK22(6.659,4.952) AK23(5.786,4.952) AK25(4.81,4.952) AK26(3.858,4.952) AK28(2.905,4.952) AK29(2.004,4.952) AK32(0.49,4.952) AK33(-0.412,4.952) AK35(-1.415,4.952) AK36(-2.266,4.952) AK38(-3.295,4.952) AK40(-4.792,4.952) AK42(-5.63,4.952) AK43(-6.582,4.952) AK45(-7.56,4.952) AK46(-8.462,4.952) AK48(-9.516,4.952) AK49(-10.418,4.952) AK51(-11.421,4.952) AK52(-12.269,4.952) AK54(-13.295,4.952) AK55(-14.248,4.952) AK57(-15.195,4.952) AK58(-16.094,4.952)
BSH-030-01-L-D-A-TR-60P-LDH
  round 1.016 hole 1.016 unplated: (-10.063,-2.666) (10.063,-2.666)
  rect 0.279x2.261 smd: 1(-7.25,-2.864) 2(-6.75,-2.864) 3(-6.25,-2.864) 4(-5.75,-2.864) 5(-5.25,-2.864) 6(-4.75,-2.864) 7(-4.25,-2.864) 8(-3.75,-2.864) 9(-3.25,-2.864) 10(-2.75,-2.864) 11(-2.25,-2.864) 12(-1.75,-2.864) 13(-1.25,-2.864) 14(-0.75,-2.864) 15(-0.25,-2.864) 16(0.25,-2.864) 17(0.75,-2.864) 18(1.25,-2.864) 19(1.75,-2.864) 20(2.25,-2.864) 21(2.75,-2.864) 22(3.25,-2.864) 23(3.75,-2.864) 24(4.25,-2.864) 25(4.75,-2.864) 26(5.25,-2.864) 27(5.75,-2.864) 28(6.25,-2.864) 29(6.75,-2.864) 30(7.25,-2.864) 31(7.25,2.864) 32(6.75,2.864) 33(6.25,2.864) 34(5.75,2.864) 35(5.25,2.864) 36(4.75,2.864) 37(4.25,2.864) 38(3.75,2.864) 39(3.25,2.864) 40(2.75,2.864) 41(2.25,2.864) 42(1.75,2.864) 43(1.25,2.864) 44(0.75,2.864) 45(0.25,2.864) 46(-0.25,2.864) 47(-0.75,2.864) 48(-1.25,2.864) 49(-1.75,2.864) 50(-2.25,2.864) 51(-2.75,2.864) 52(-3.25,2.864) 53(-3.75,2.864) 54(-4.25,2.864) 55(-4.75,2.864) 56(-5.25,2.864) 57(-5.75,2.864) 58(-6.25,2.864) 59(-6.75,2.864) 60(-7.25,2.864)
CC0402
  custom 0.12x0.12 smd: 1(0.39,0) 2(-0.39,0)
CC0603
  rect 0.813x0.711 smd: 1(0.737,0) 2(-0.737,0)
CC0805
  rect 0.94x1.346 smd: 1(0.895,0) 2(-0.895,0)
CC1808
  rect 2.159x2.286 smd: 1(-2.349,0) 2(2.349,0)
CHOKE-ETQP4L
  rect 2.896x4.293 smd: 1(-4.216,0) 2(4.216,0)
CHOKE-LQH32PN4R7NN0L
  rect 1.245x2.007 smd: 1(-1.275,0) 2(1.275,0)
CHOKE-MPL73-1R5
  rect 1.676x3.404 smd: 1(-2.843,0) 2(2.843,0)
CHOKE-WCM2012-4P
  rect 0.889x0.406 smd: 1(-0.85,0.4) 2(0.85,0.4) 3(0.85,-0.4) 4(-0.85,-0.4)
D-DO-214AC
  rect 1.88x2.032 smd: 1(-2.1,0) 2(2.1,0)
D-SOD523-1_2X0_8-0_7H
  rect 0.61x0.787 smd: 1(-0.75,0) 2(0.75,0)
DDR-DDRRK-20401-TP4B-204P-RUV
  round 1.092 hole 1.092 unplated: (-33.4,0)
  round 1.6 hole 1.6 unplated: (33.4,0)
  rect 0.356x2.007 smd: 1(31.65,4.1) 2(31.35,-4.1) 3(31.05,4.1) 4(30.75,-4.1) 5(30.45,4.1) 6(30.15,-4.1) 7(29.85,4.1) 8(29.55,-4.1) 9(29.25,4.1) 10(28.95,-4.1) 11(28.65,4.1) 12(28.35,-4.1) 13(28.05,4.1) 14(27.75,-4.1) 15(27.45,4.1) 16(27.15,-4.1) 17(26.85,4.1) 18(26.55,-4.1) 19(26.25,4.1) 20(25.95,-4.1) 21(25.65,4.1) 22(25.35,-4.1) 23(25.05,4.1) 24(24.75,-4.1) 25(24.45,4.1) 26(24.15,-4.1) 27(23.85,4.1) 28(23.55,-4.1) 29(23.25,4.1) 30(22.95,-4.1) 31(22.65,4.1) 32(22.35,-4.1) 33(22.05,4.1) 34(21.75,-4.1) 35(21.45,4.1) 36(21.15,-4.1) 37(20.85,4.1) 38(20.55,-4.1) 39(20.25,4.1) 40(19.95,-4.1) 41(19.65,4.1) 42(19.35,-4.1) 43(19.05,4.1) 44(18.75,-4.1) 45(18.45,4.1) 46(18.15,-4.1) 47(17.85,4.1) 48(17.55,-4.1) 49(17.25,4.1) 50(16.95,-4.1) 51(16.65,4.1) 52(16.35,-4.1) 53(16.05,4.1) 54(15.75,-4.1) 55(15.45,4.1) 56(15.15,-4.1) 57(14.85,4.1) 58(14.55,-4.1) 59(14.25,4.1) 60(13.95,-4.1) 61(13.65,4.1) 62(13.35,-4.1) 63(13.05,4.1) 64(12.75,-4.1) 65(12.45,4.1) 66(12.15,-4.1) 67(11.85,4.1) 68(11.55,-4.1) 69(11.25,4.1) 70(10.95,-4.1) 71(10.65,4.1) 72(10.35,-4.1) 73(7.65,4.1) 74(7.35,-4.1) 75(7.05,4.1) 76(6.75,-4.1) 77(6.45,4.1) 78(6.15,-4.1) 79(5.85,4.1) 80(5.55,-4.1) 81(5.25,4.1) 82(4.95,-4.1) 83(4.65,4.1) 84(4.35,-4.1) 85(4.05,4.1) 86(3.75,-4.1) 87(3.45,4.1) 88(3.15,-4.1) 89(2.85,4.1) 90(2.55,-4.1) 91(2.25,4.1) 92(1.95,-4.1) 93(1.65,4.1) 94(1.35,-4.1) 95(1.05,4.1) 96(0.75,-4.1) 97(0.45,4.1) 98(0.15,-4.1) 99(-0.15,4.1) 100(-0.45,-4.1) 101(-0.75,4.1) 102(-1.05,-4.1) 103(-1.35,4.1) 104(-1.65,-4.1) 105(-1.95,4.1) 106(-2.25,-4.1) 107(-2.55,4.1) 108(-2.85,-4.1) 109(-3.15,4.1) 110(-3.45,-4.1) 111(-3.75,4.1) 112(-4.05,-4.1) 113(-4.35,4.1) 114(-4.65,-4.1) 115(-4.95,4.1) 116(-5.25,-4.1) 117(-5.55,4.1) 118(-5.85,-4.1) 119(-6.15,4.1) 120(-6.45,-4.1) 121(-6.75,4.1) 122(-7.05,-4.1) 123(-7.35,4.1) 124(-7.65,-4.1) 125(-7.95,4.1) 126(-8.25,-4.1) 127(-8.55,4.1) 128(-8.85,-4.1) 129(-9.15,4.1) 130(-9.45,-4.1) 131(-9.75,4.1) 132(-10.05,-4.1) 133(-10.35,4.1) 134(-10.65,-4.1) 135(-10.95,4.1) 136(-11.25,-4.1) 137(-11.55,4.1) 138(-11.85,-4.1) 139(-12.15,4.1) 140(-12.45,-4.1) 141(-12.75,4.1) 142(-13.05,-4.1) 143(-13.35,4.1) 144(-13.65,-4.1) 145(-13.95,4.1) 146(-14.25,-4.1) 147(-14.55,4.1) 148(-14.85,-4.1) 149(-15.15,4.1) 150(-15.45,-4.1) 151(-15.75,4.1) 152(-16.05,-4.1) 153(-16.35,4.1) 154(-16.65,-4.1) 155(-16.95,4.1) 156(-17.25,-4.1) 157(-17.55,4.1) 158(-17.85,-4.1) 159(-18.15,4.1) 160(-18.45,-4.1) 161(-18.75,4.1) 162(-19.05,-4.1) 163(-19.35,4.1) 164(-19.65,-4.1) 165(-19.95,4.1) 166(-20.25,-4.1) 167(-20.55,4.1) 168(-20.85,-4.1) 169(-21.15,4.1) 170(-21.45,-4.1) 171(-21.75,4.1) 172(-22.05,-4.1) 173(-22.35,4.1) 174(-22.65,-4.1) 175(-22.95,4.1) 176(-23.25,-4.1) 177(-23.55,4.1) 178(-23.85,-4.1) 179(-24.15,4.1) 180(-24.45,-4.1) 181(-24.75,4.1) 182(-25.05,-4.1) 183(-25.35,4.1) 184(-25.65,-4.1) 185(-25.95,4.1) 186(-26.25,-4.1) 187(-26.55,4.1) 188(-26.85,-4.1) 189(-27.15,4.1) 190(-27.45,-4.1) 191(-27.75,4.1) 192(-28.05,-4.1) 193(-28.35,4.1) 194(-28.65,-4.1) 195(-28.95,4.1) 196(-29.25,-4.1) 197(-29.55,4.1) 198(-29.85,-4.1) 199(-30.15,4.1) 200(-30.45,-4.1) 201(-30.75,4.1) 202(-31.05,-4.1) 203(-31.35,4.1) 204(-31.65,-4.1)
  rect 4.496x4.597 smd: 207(32.55,12) 208(-32.55,12)
DDR-DDRSK-20401-TP4B-204P-LDV
  round 1.6 hole 1.6 unplated: (-33.4,0)
  round 1.092 hole 1.092 unplated: (33.4,0)
  rect 0.356x2.007 smd: 1(-31.65,-4.1) 2(-31.35,4.1) 3(-31.05,-4.1) 4(-30.75,4.1) 5(-30.45,-4.1) 6(-30.15,4.1) 7(-29.85,-4.1) 8(-29.55,4.1) 9(-29.25,-4.1) 10(-28.95,4.1) 11(-28.65,-4.1) 12(-28.35,4.1) 13(-28.05,-4.1) 14(-27.75,4.1) 15(-27.45,-4.1) 16(-27.15,4.1) 17(-26.85,-4.1) 18(-26.55,4.1) 19(-26.25,-4.1) 20(-25.95,4.1) 21(-25.65,-4.1) 22(-25.35,4.1) 23(-25.05,-4.1) 24(-24.75,4.1) 25(-24.45,-4.1) 26(-24.15,4.1) 27(-23.85,-4.1) 28(-23.55,4.1) 29(-23.25,-4.1) 30(-22.95,4.1) 31(-22.65,-4.1) 32(-22.35,4.1) 33(-22.05,-4.1) 34(-21.75,4.1) 35(-21.45,-4.1) 36(-21.15,4.1) 37(-20.85,-4.1) 38(-20.55,4.1) 39(-20.25,-4.1) 40(-19.95,4.1) 41(-19.65,-4.1) 42(-19.35,4.1) 43(-19.05,-4.1) 44(-18.75,4.1) 45(-18.45,-4.1) 46(-18.15,4.1) 47(-17.85,-4.1) 48(-17.55,4.1) 49(-17.25,-4.1) 50(-16.95,4.1) 51(-16.65,-4.1) 52(-16.35,4.1) 53(-16.05,-4.1) 54(-15.75,4.1) 55(-15.45,-4.1) 56(-15.15,4.1) 57(-14.85,-4.1) 58(-14.55,4.1) 59(-14.25,-4.1) 60(-13.95,4.1) 61(-13.65,-4.1) 62(-13.35,4.1) 63(-13.05,-4.1) 64(-12.75,4.1) 65(-12.45,-4.1) 66(-12.15,4.1) 67(-11.85,-4.1) 68(-11.55,4.1) 69(-11.25,-4.1) 70(-10.95,4.1) 71(-10.65,-4.1) 72(-10.35,4.1) 73(-7.65,-4.1) 74(-7.35,4.1) 75(-7.05,-4.1) 76(-6.75,4.1) 77(-6.45,-4.1) 78(-6.15,4.1) 79(-5.85,-4.1) 80(-5.55,4.1) 81(-5.25,-4.1) 82(-4.95,4.1) 83(-4.65,-4.1) 84(-4.35,4.1) 85(-4.05,-4.1) 86(-3.75,4.1) 87(-3.45,-4.1) 88(-3.15,4.1) 89(-2.85,-4.1) 90(-2.55,4.1) 91(-2.25,-4.1) 92(-1.95,4.1) 93(-1.65,-4.1) 94(-1.35,4.1) 95(-1.05,-4.1) 96(-0.75,4.1) 97(-0.45,-4.1) 98(-0.15,4.1) 99(0.15,-4.1) 100(0.45,4.1) 101(0.75,-4.1) 102(1.05,4.1) 103(1.35,-4.1) 104(1.65,4.1) 105(1.95,-4.1) 106(2.25,4.1) 107(2.55,-4.1) 108(2.85,4.1) 109(3.15,-4.1) 110(3.45,4.1) 111(3.75,-4.1) 112(4.05,4.1) 113(4.35,-4.1) 114(4.65,4.1) 115(4.95,-4.1) 116(5.25,4.1) 117(5.55,-4.1) 118(5.85,4.1) 119(6.15,-4.1) 120(6.45,4.1) 121(6.75,-4.1) 122(7.05,4.1) 123(7.35,-4.1) 124(7.65,4.1) 125(7.95,-4.1) 126(8.25,4.1) 127(8.55,-4.1) 128(8.85,4.1) 129(9.15,-4.1) 130(9.45,4.1) 131(9.75,-4.1) 132(10.05,4.1) 133(10.35,-4.1) 134(10.65,4.1) 135(10.95,-4.1) 136(11.25,4.1) 137(11.55,-4.1) 138(11.85,4.1) 139(12.15,-4.1) 140(12.45,4.1) 141(12.75,-4.1) 142(13.05,4.1) 143(13.35,-4.1) 144(13.65,4.1) 145(13.95,-4.1) 146(14.25,4.1) 147(14.55,-4.1) 148(14.85,4.1) 149(15.15,-4.1) 150(15.45,4.1) 151(15.75,-4.1) 152(16.05,4.1) 153(16.35,-4.1) 154(16.65,4.1) 155(16.95,-4.1) 156(17.25,4.1) 157(17.55,-4.1) 158(17.85,4.1) 159(18.15,-4.1) 160(18.45,4.1) 161(18.75,-4.1) 162(19.05,4.1) 163(19.35,-4.1) 164(19.65,4.1) 165(19.95,-4.1) 166(20.25,4.1) 167(20.55,-4.1) 168(20.85,4.1) 169(21.15,-4.1) 170(21.45,4.1) 171(21.75,-4.1) 172(22.05,4.1) 173(22.35,-4.1) 174(22.65,4.1) 175(22.95,-4.1) 176(23.25,4.1) 177(23.55,-4.1) 178(23.85,4.1) 179(24.15,-4.1) 180(24.45,4.1) 181(24.75,-4.1) 182(25.05,4.1) 183(25.35,-4.1) 184(25.65,4.1) 185(25.95,-4.1) 186(26.25,4.1) 187(26.55,-4.1) 188(26.85,4.1) 189(27.15,-4.1) 190(27.45,4.1) 191(27.75,-4.1) 192(28.05,4.1) 193(28.35,-4.1) 194(28.65,4.1) 195(28.95,-4.1) 196(29.25,4.1) 197(29.55,-4.1) 198(29.85,4.1) 199(30.15,-4.1) 200(30.45,4.1) 201(30.75,-4.1) 202(31.05,4.1) 203(31.35,-4.1) 204(31.65,4.1)
  rect 4.496x4.597 smd: 205(-32.55,12) 206(32.55,12)
DSM
  rect 1.016x0.508 smd: 1(-1.3,0) 2(1.321,0)
ECAP5X5_8-5_9-2P
  rect 2.997x1.6 smd: 1(2.2,0) 2(-2.2,0)
ECAP6D3S
  rect 0.991x3.099 smd: 1(0,-2.565) 2(0,2.565)
F3_2X1_65-2_8
  rect 0.991x1.803 smd: 1(-1.4,0) 2(1.4,0)
FSMD1206P150TS
  rect 1.016x1.803 smd: 1(-1.725,0) 2(1.725,0)
H-C98D98N
  round 2.489 hole 2.489 unplated: (0,0)
H-C236D118P2
  round 5.994 hole 2.997: 1(0,0)
H-C236D146P2
  round 5.994 hole 3.708: 1(0,0)
H-C394D354P2
  round 10.008 hole 8.992: 1(0,0)
H-TC177BC197D102P2
  round 5.004 hole 2.591: 1(0,0)
H-TC236BC102D102PT
  round 2.591 hole 2.591: 1(0,0)
H-TC236BC315D118P2
  round 5.994 hole 2.997: 1(0,0)
H-TC236IC102BC236D102P2
  round 5.994 hole 2.591: 1(0,0)
H-TC256IC118BC315D118P2
  round 6.502 hole 2.997: 1(0,0)
H-TC276BC197D142P2
  round 7.01 hole 3.607: 1(0,0)
HDMI-HMRBL-AK520C-19P
  round 0.787 hole 0.559: 1(-4.5,8.15) 2(-4,9.7) 3(-3.5,8.15) 4(-3,9.7) 5(-2.5,8.15) 6(-2,9.7) 7(-1.5,8.15) 8(-1,9.7) 9(-0.5,8.15) 10(0,9.7) 11(0.5,8.15) 12(1,9.7) 13(1.5,8.15) 14(2,9.7) 15(2.5,8.15) 16(3,9.7) 17(3.5,8.15) 18(4,9.7) 19(4.5,8.15)
  oval 1.397x2.108 hole 0.787x1.499: 20(-7.25,8.35) 21(7.25,8.35)
  oval 1.702x2.896 hole 1.092x2.311: 22(-8.75,0) 23(8.75,0)
INTEL-BKT-SHARK-ULT
  round 7.188 hole 3.759: 1(-26,14) 2(26,14)
  round 7.188 hole 3.607: 3(26,-14)
  round 7.01 hole 3.81x3.607: 4(-26,-14)
L3_2X2_5-1_55
  rect 1.245x2.007 smd: 1(-1.275,0) 2(1.275,0)
LGA16-3X3-5-HP3DC2TR
  rect 0.305x0.457 smd: 1(-1,-1.225) 2(-0.5,-1.225) 3(0,-1.225) 4(0.5,-1.225) 5(1,-1.225) 9(1,1.225) 10(0.5,1.225) 11(0,1.225) 12(-0.5,1.225) 13(-1,1.225)
  rect 0.457x0.305 smd: 6(1.225,-0.5) 7(1.225,0) 8(1.225,0.5) 14(-1.225,0.5) 15(-1.225,0) 16(-1.225,-0.5)
LQFP128-16X16-4
  rect 0.203x1.499 smd: 1(-6.2,-7.85) 2(-5.8,-7.85) 3(-5.4,-7.85) 4(-5,-7.85) 5(-4.6,-7.85) 6(-4.2,-7.85) 7(-3.8,-7.85) 8(-3.4,-7.85) 9(-3,-7.85) 10(-2.6,-7.85) 11(-2.2,-7.85) 12(-1.8,-7.85) 13(-1.4,-7.85) 14(-1,-7.85) 15(-0.6,-7.85) 16(-0.2,-7.85) 17(0.2,-7.85) 18(0.6,-7.85) 19(1,-7.85) 20(1.4,-7.85) 21(1.8,-7.85) 22(2.2,-7.85) 23(2.6,-7.85) 24(3,-7.85) 25(3.4,-7.85) 26(3.8,-7.85) 27(4.2,-7.85) 28(4.6,-7.85) 29(5,-7.85) 30(5.4,-7.85) 31(5.8,-7.85) 32(6.2,-7.85) 65(6.2,7.85) 66(5.8,7.85) 67(5.4,7.85) 68(5,7.85) 69(4.6,7.85) 70(4.2,7.85) 71(3.8,7.85) 72(3.4,7.85) 73(3,7.85) 74(2.6,7.85) 75(2.2,7.85) 76(1.8,7.85) 77(1.4,7.85) 78(1,7.85) 79(0.6,7.85) 80(0.2,7.85) 81(-0.2,7.85) 82(-0.6,7.85) 83(-1,7.85) 84(-1.4,7.85) 85(-1.8,7.85) 86(-2.2,7.85) 87(-2.6,7.85) 88(-3,7.85) 89(-3.4,7.85) 90(-3.8,7.85) 91(-4.2,7.85) 92(-4.6,7.85) 93(-5,7.85) 94(-5.4,7.85) 95(-5.8,7.85) 96(-6.2,7.85)
  rect 1.499x0.203 smd: 33(7.85,-6.2) 34(7.85,-5.8) 35(7.85,-5.4) 36(7.85,-5) 37(7.85,-4.6) 38(7.85,-4.2) 39(7.85,-3.8) 40(7.85,-3.4) 41(7.85,-3) 42(7.85,-2.6) 43(7.85,-2.2) 44(7.85,-1.8) 45(7.85,-1.4) 46(7.85,-1) 47(7.85,-0.6) 48(7.85,-0.2) 49(7.85,0.2) 50(7.85,0.6) 51(7.85,1) 52(7.85,1.4) 53(7.85,1.8) 54(7.85,2.2) 55(7.85,2.6) 56(7.85,3) 57(7.85,3.4) 58(7.85,3.8) 59(7.85,4.2) 60(7.85,4.6) 61(7.85,5) 62(7.85,5.4) 63(7.85,5.8) 64(7.85,6.2) 97(-7.85,6.2) 98(-7.85,5.8) 99(-7.85,5.4) 100(-7.85,5) 101(-7.85,4.6) 102(-7.85,4.2) 103(-7.85,3.8) 104(-7.85,3.4) 105(-7.85,3) 106(-7.85,2.6) 107(-7.85,2.2) 108(-7.85,1.8) 109(-7.85,1.4) 110(-7.85,1) 111(-7.85,0.6) 112(-7.85,0.2) 113(-7.85,-0.2) 114(-7.85,-0.6) 115(-7.85,-1) 116(-7.85,-1.4) 117(-7.85,-1.8) 118(-7.85,-2.2) 119(-7.85,-2.6) 120(-7.85,-3) 121(-7.85,-3.4) 122(-7.85,-3.8) 123(-7.85,-4.2) 124(-7.85,-4.6) 125(-7.85,-5) 126(-7.85,-5.4) 127(-7.85,-5.8) 128(-7.85,-6.2)
MINICARD-110021-52131-52P-RUV
  round 1.092 hole 1.092 unplated: (-12.5,0)
  round 1.6 hole 1.6 unplated: (12.5,0)
  rect 0.508x2.007 smd: 1(11.8,4.1) 2(11.4,-4.1) 3(11,4.1) 4(10.6,-4.1) 5(10.2,4.1) 6(9.8,-4.1) 7(9.4,4.1) 8(9,-4.1) 9(8.6,4.1) 10(8.2,-4.1) 11(7.8,4.1) 12(7.4,-4.1) 13(7,4.1) 14(6.6,-4.1) 15(6.2,4.1) 16(5.8,-4.1) 17(2.2,4.1) 18(1.8,-4.1) 19(1.4,4.1) 20(1,-4.1) 21(0.6,4.1) 22(0.2,-4.1) 23(-0.2,4.1) 24(-0.6,-4.1) 25(-1,4.1) 26(-1.4,-4.1) 27(-1.8,4.1) 28(-2.2,-4.1) 29(-2.6,4.1) 30(-3,-4.1) 31(-3.4,4.1) 32(-3.8,-4.1) 33(-4.2,4.1) 34(-4.6,-4.1) 35(-5,4.1) 36(-5.4,-4.1) 37(-5.8,4.1) 38(-6.2,-4.1) 39(-6.6,4.1) 40(-7,-4.1) 41(-7.4,4.1) 42(-7.8,-4.1) 43(-8.2,4.1) 44(-8.6,-4.1) 45(-9,4.1) 46(-9.4,-4.1) 47(-9.8,4.1) 48(-10.2,-4.1) 49(-10.6,4.1) 50(-11,-4.1) 51(-11.4,4.1) 52(-11.8,-4.1)
  rect 2.311x3.2 smd: 53(14.65,3.5) 54(-14.65,3.5)
MINIPCI-80053-1023-52P-SMT
  round 1.6 hole 1.6 unplated: (-12.5,0) (12.5,0)
  oval 0.61x0.864 hole 0.406x0.61: 1(-11.8,-2.3) 3(-11,-2.3) 5(-10.2,-2.3) 7(-9.4,-2.3) 9(-8.6,-2.3) 11(-7.8,-2.3) 13(-7,-2.3) 15(-6.2,-2.3) 17(-2.2,-2.3) 19(-1.4,-2.3) 21(-0.6,-2.3) 23(0.2,-2.3) 25(1,-2.3) 27(1.8,-2.3) 29(2.6,-2.3) 31(3.4,-2.3) 33(4.2,-2.3) 35(5,-2.3) 37(5.8,-2.3) 39(6.6,-2.3) 41(7.4,-2.3) 43(8.2,-2.3) 45(9,-2.3) 47(9.8,-2.3) 49(10.6,-2.3) 51(11.4,-2.3)
  rect 0.508x2.007 smd: 2(-11.4,3.23) 4(-10.6,3.23) 6(-9.8,3.23) 8(-9,3.23) 10(-8.2,3.23) 12(-7.4,3.23) 14(-6.6,3.23) 16(-5.8,3.23) 18(-1.8,3.23) 20(-1,3.23) 22(-0.2,3.23) 24(0.6,3.23) 26(1.4,3.23) 28(2.2,3.23) 30(3,3.23) 32(3.8,3.23) 34(4.6,3.23) 36(5.4,3.23) 38(6.2,3.23) 40(7,3.23) 42(7.8,3.23) 44(8.6,3.23) 46(9.4,3.23) 48(10.2,3.23) 50(11,3.23) 52(11.8,3.23)
  rect 2.311x3.2 smd: 53(-14.94,-1.55) 54(14.94,-1.55)
MIPCI-APCI0020-P003H-75P-KM
  round 1.6 hole 1.6 unplated: (-10,0)
  round 1.092 hole 1.092 unplated: (10,0)
  rect 0.305x1.549 smd: 1(9.25,-5.275) 2(9,2.275) 3(8.75,-5.275) 4(8.5,2.275) 5(8.25,-5.275) 6(8,2.275) 7(7.75,-5.275) 8(7.5,2.275) 9(7.25,-5.275) 10(7,2.275) 11(6.75,-5.275) 12(6.5,2.275) 13(6.25,-5.275) 14(6,2.275) 15(5.75,-5.275) 16(5.5,2.275) 17(5.25,-5.275) 18(5,2.275) 19(4.75,-5.275) 20(4.5,2.275) 21(4.25,-5.275) 22(4,2.275) 23(3.75,-5.275) 24(3.5,2.275) 25(3.25,-5.275) 26(3,2.275) 27(2.75,-5.275) 28(2.5,2.275) 29(2.25,-5.275) 30(2,2.275) 31(1.75,-5.275) 32(1.5,2.275) 33(1.25,-5.275) 34(1,2.275) 35(0.75,-5.275) 36(0.5,2.275) 37(0.25,-5.275) 38(0,2.275) 39(-0.25,-5.275) 40(-0.5,2.275) 41(-0.75,-5.275) 42(-1,2.275) 43(-1.25,-5.275) 44(-1.5,2.275) 45(-1.75,-5.275) 46(-2,2.275) 47(-2.25,-5.275) 48(-2.5,2.275) 49(-2.75,-5.275) 50(-3,2.275) 51(-3.25,-5.275) 52(-3.5,2.275) 53(-3.75,-5.275) 54(-4,2.275) 55(-4.25,-5.275) 56(-4.5,2.275) 57(-4.75,-5.275) 58(-5,2.275) 67(-7.25,-5.275) 68(-7.5,2.275) 69(-7.75,-5.275) 70(-8,2.275) 71(-8.25,-5.275) 72(-8.5,2.275) 73(-8.75,-5.275) 74(-9,2.275) 75(-9.25,-5.275)
  rect 1.194x2.743 smd: 76(10.35,-4.5) 77(-10.35,-4.5)
MSOP8-4_9-65
  rect 0.406x1.448 smd: 1(-0.975,-2.325) 2(-0.325,-2.325) 3(0.325,-2.325) 4(0.975,-2.325) 5(0.975,2.325) 6(0.325,2.325) 7(-0.325,2.325) 8(-0.975,2.325)
O-U83A-1
  round 5.004 hole 5.004 unplated: (0,0)
O-U83B-4
  round 5.994 hole 2.997: 1(0,0)
O-U83B-5
  round 8.001 hole 3.2: 1(0,0)
O-Y11-1
  custom 1.45x1.45 hole 2.997: 1(0,0)
  round 2.997 hole 2.997: 2(-10.2,0.15)
O-Y11A-2
  custom 1.375x1.375 hole 2.997: 1(3.81,1.27)
  round 2.997 hole 2.997: 2(8.81,1.27)
O-Y12A-4
  custom 1.5x1.5 hole 2.997: 1(0,0)
O-Y12A-5
  custom 2.5x2.5 hole 2.997: 1(0,0)
O-Y12A-7
  custom 1.375x1.375 hole 2.997: 1(0,0)
PG-TSDSON-8-8P-R
  rect 0.787x0.33 smd: 1(1.5,-0.975) 2(1.5,-0.325) 3(1.5,0.325) 4(1.5,0.975)
  custom 0.573x0.573 smd: 5(-0.72,0)
  rect 0.66x0.33 smd: 6(-1.575,0.325) 7(-1.575,-0.325) 8(-1.575,-0.975)
PVQFN20-3_5X3_5-5-25P
  rect 0.279x0.838 smd: 1(-1,-1.725) 2(-0.5,-1.725) 3(0,-1.725) 4(0.5,-1.725) 5(1,-1.725) 11(1,1.725) 12(0.5,1.725) 13(0,1.725) 14(-0.5,1.725) 15(-1,1.725)
  rect 0.838x0.279 smd: 6(1.725,-1) 7(1.725,-0.5) 8(1.725,0) 9(1.725,0.5) 10(1.725,1) 16(-1.725,1) 17(-1.725,0.5) 18(-1.725,0) 19(-1.725,-0.5) 20(-1.725,-1)
  rect 2.057x2.057 smd: 21(0,0)
  round 0.61 hole 0.305: 22(-0.5,-0.5) 23(0.5,-0.5) 24(0.5,0.5) 25(-0.5,0.5)
PWQFN20-4X4-5-30P
  rect 0.279x0.838 smd: 1(1,1.975) 2(0.5,1.975) 3(0,1.975) 4(-0.5,1.975) 5(-1,1.975) 11(-1,-1.975) 12(-0.5,-1.975) 13(0,-1.975) 14(0.5,-1.975) 15(1,-1.975)
  rect 0.838x0.279 smd: 6(-1.975,1) 7(-1.975,0.5) 8(-1.975,0) 9(-1.975,-0.5) 10(-1.975,-1) 16(1.975,-1) 17(1.975,-0.5) 18(1.975,0) 19(1.975,0.5) 20(1.975,1)
  rect 2.692x2.692 smd: 21(0,0)
  round 0.61 hole 0.305: 22(-0.9,0.9) 23(0,0.9) 24(0.9,0.9) 25(-0.9,0) 26(0,0) 27(0.9,0) 28(-0.9,-0.9) 29(0,-0.9) 30(0.9,-0.9)
QFN10-3X3-45
  rect 0.61x0.254 smd: 1(-1.35,-1.125) 2(-1.35,-0.675) 3(-1.35,-0.225) 4(-1.35,0.225) 5(-1.35,0.675) 6(-1.35,1.125)
  rect 0.254x1.168 smd: 7(-0.675,1.065)
  rect 2.007x0.914 smd: 8(0.65,0.94)
  custom 0.482x0.482 smd: 9(0,0)
  rect 1.143x0.787 smd: 10(0.25,-1.012)
QFN16-3X3-5-17P-WM9001
  rect 0.965x0.305 smd: 1(-1.612,0.75) 2(-1.612,0.25) 3(-1.612,-0.25) 4(-1.612,-0.75) 9(1.612,-0.75) 10(1.612,-0.25) 11(1.612,0.25) 12(1.612,0.75)
  rect 0.305x0.965 smd: 5(-0.75,-1.612) 6(-0.25,-1.612) 7(0.25,-1.612) 8(0.75,-1.612) 13(0.75,1.612) 14(0.25,1.612) 15(-0.25,1.612) 16(-0.75,1.612)
  rect 1.702x1.702 smd: 17(0,0)
QFN23-4X4-5
  rect 0.457x0.254 smd: 1(-1.825,1.25) 2(-1.825,0.75) 3(-1.825,0.25) 4(-1.825,-0.25) 5(-1.825,-0.75) 6(-1.825,-1.25) 12(1.825,-1.25) 13(1.825,-0.75) 14(1.825,-0.25) 15(1.825,0.25) 16(1.825,0.75) 17(1.825,1.25)
  rect 0.254x0.457 smd: 7(-1.25,-1.825) 8(-0.75,-1.825) 10(0.75,-1.825) 18(1.25,1.825) 19(0.75,1.825) 20(0.25,1.825) 21(-0.25,1.825) 22(-0.75,1.825) 23(-1.25,1.825)
  custom 0.335x0.335 smd: 9(-0.67,-0.335)
  custom 0.249x0.249 smd: 11(0.867,-0.335)
QFN28-4X4-4-29P-NCP81101MNTWG
  rect 0.965x0.203 smd: 1(-2.03,1.2) 2(-2.03,0.8) 3(-2.03,0.4) 4(-2.03,0) 5(-2.03,-0.4) 6(-2.03,-0.8) 7(-2.03,-1.2) 15(2.03,-1.2) 16(2.03,-0.8) 17(2.03,-0.4) 18(2.03,0) 19(2.03,0.4) 20(2.03,0.8) 21(2.03,1.2)
  rect 0.203x0.965 smd: 8(-1.2,-2.03) 9(-0.8,-2.03) 10(-0.4,-2.03) 11(0,-2.03) 12(0.4,-2.03) 13(0.8,-2.03) 14(1.2,-2.03) 22(1.2,2.03) 23(0.8,2.03) 24(0.4,2.03) 25(0,2.03) 26(-0.4,2.03) 27(-0.8,2.03) 28(-1.2,2.03)
  rect 2.718x2.718 smd: 29(0,0)
QFN32-4X4-4-33P-0_9H
  custom 0.051x0.051 smd: 1(-1.4,-2.1) 8(1.4,-2.1) 9(2.1,-1.4) 16(2.1,1.4) 17(1.4,2.1) 24(-1.4,2.1) 25(-2.1,1.4) 32(-2.1,-1.4)
  rect 0.203x0.991 smd: 2(-1,-2.1) 3(-0.6,-2.1) 4(-0.2,-2.1) 5(0.2,-2.1) 6(0.6,-2.1) 7(1,-2.1) 18(1,2.1) 19(0.6,2.1) 20(0.2,2.1) 21(-0.2,2.1) 22(-0.6,2.1) 23(-1,2.1)
  rect 0.991x0.203 smd: 10(2.1,-1) 11(2.1,-0.6) 12(2.1,-0.2) 13(2.1,0.2) 14(2.1,0.6) 15(2.1,1) 26(-2.1,1) 27(-2.1,0.6) 28(-2.1,0.2) 29(-2.1,-0.2) 30(-2.1,-0.6) 31(-2.1,-1)
  rect 2.692x2.692 smd: 33(0,0)
QFN32-4X4-5-33P-RTS5227-GRT
  custom 0.051x0.051 smd: 1(-2.1,1.4) 8(-2.1,-1.4) 9(-1.4,-2.1) 16(1.4,-2.1) 17(2.1,-1.4) 24(2.1,1.4) 25(1.4,2.1) 32(-1.4,2.1)
  rect 0.991x0.203 smd: 2(-2.1,1) 3(-2.1,0.6) 4(-2.1,0.2) 5(-2.1,-0.2) 6(-2.1,-0.6) 7(-2.1,-1) 18(2.1,-1) 19(2.1,-0.6) 20(2.1,-0.2) 21(2.1,0.2) 22(2.1,0.6) 23(2.1,1)
  rect 0.203x0.991 smd: 10(-1,-2.1) 11(-0.6,-2.1) 12(-0.2,-2.1) 13(0.2,-2.1) 14(0.6,-2.1) 15(1,-2.1) 26(1,2.1) 27(0.6,2.1) 28(0.2,2.1) 29(-0.2,2.1) 30(-0.6,2.1) 31(-1,2.1)
  rect 2.692x2.692 smd: 33(0,0)
QFN48-7X7-5-49P-1H
  rect 0.305x0.991 smd: 1(-2.75,-3.6) 2(-2.25,-3.6) 3(-1.75,-3.6) 4(-1.25,-3.6) 5(-0.75,-3.6) 6(-0.25,-3.6) 7(0.25,-3.6) 8(0.75,-3.6) 9(1.25,-3.6) 10(1.75,-3.6) 11(2.25,-3.6) 12(2.75,-3.6) 25(2.75,3.6) 26(2.25,3.6) 27(1.75,3.6) 28(1.25,3.6) 29(0.75,3.6) 30(0.25,3.6) 31(-0.25,3.6) 32(-0.75,3.6) 33(-1.25,3.6) 34(-1.75,3.6) 35(-2.25,3.6) 36(-2.75,3.6)
  rect 0.991x0.305 smd: 13(3.6,-2.75) 14(3.6,-2.25) 15(3.6,-1.75) 16(3.6,-1.25) 17(3.6,-0.75) 18(3.6,-0.25) 19(3.6,0.25) 20(3.6,0.75) 21(3.6,1.25) 22(3.6,1.75) 23(3.6,2.25) 24(3.6,2.75) 37(-3.6,2.75) 38(-3.6,2.25) 39(-3.6,1.75) 40(-3.6,1.25) 41(-3.6,0.75) 42(-3.6,0.25) 43(-3.6,-0.25) 44(-3.6,-0.75) 45(-3.6,-1.25) 46(-3.6,-1.75) 47(-3.6,-2.25) 48(-3.6,-2.75)
  rect 5.639x5.639 smd: 49(0,0)
RC0402
  custom 0.12x0.12 smd: 1(0.39,0) 2(-0.39,0)
RC0603
  rect 0.813x0.711 smd: 1(0.737,0) 2(-0.737,0)
RC0805
  rect 0.94x1.346 smd: 1(0.895,0) 2(-0.895,0)
RJ45-60414-08G67-12P
  round 1.295 hole 0.889: 1(3.57,9.5) 2(2.55,8.4) 3(1.53,9.5) 4(0.51,8.4) 5(-0.51,9.5) 6(-1.53,8.4) 7(-2.55,9.5)
  round 1.194 hole 0.889: 8(-3.57,8.4)
  round 1.295 hole 0.991: 9(-4.57,7.36)
  round 1.397 hole 0.991: 10(-6.86,7.36) 11(6.86,7.36) 12(4.57,7.36)
  oval 1.727x3.404 hole 0.711x2.388: 13(9.32,0) 14(-9.32,0)
